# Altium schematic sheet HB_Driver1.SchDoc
size A4
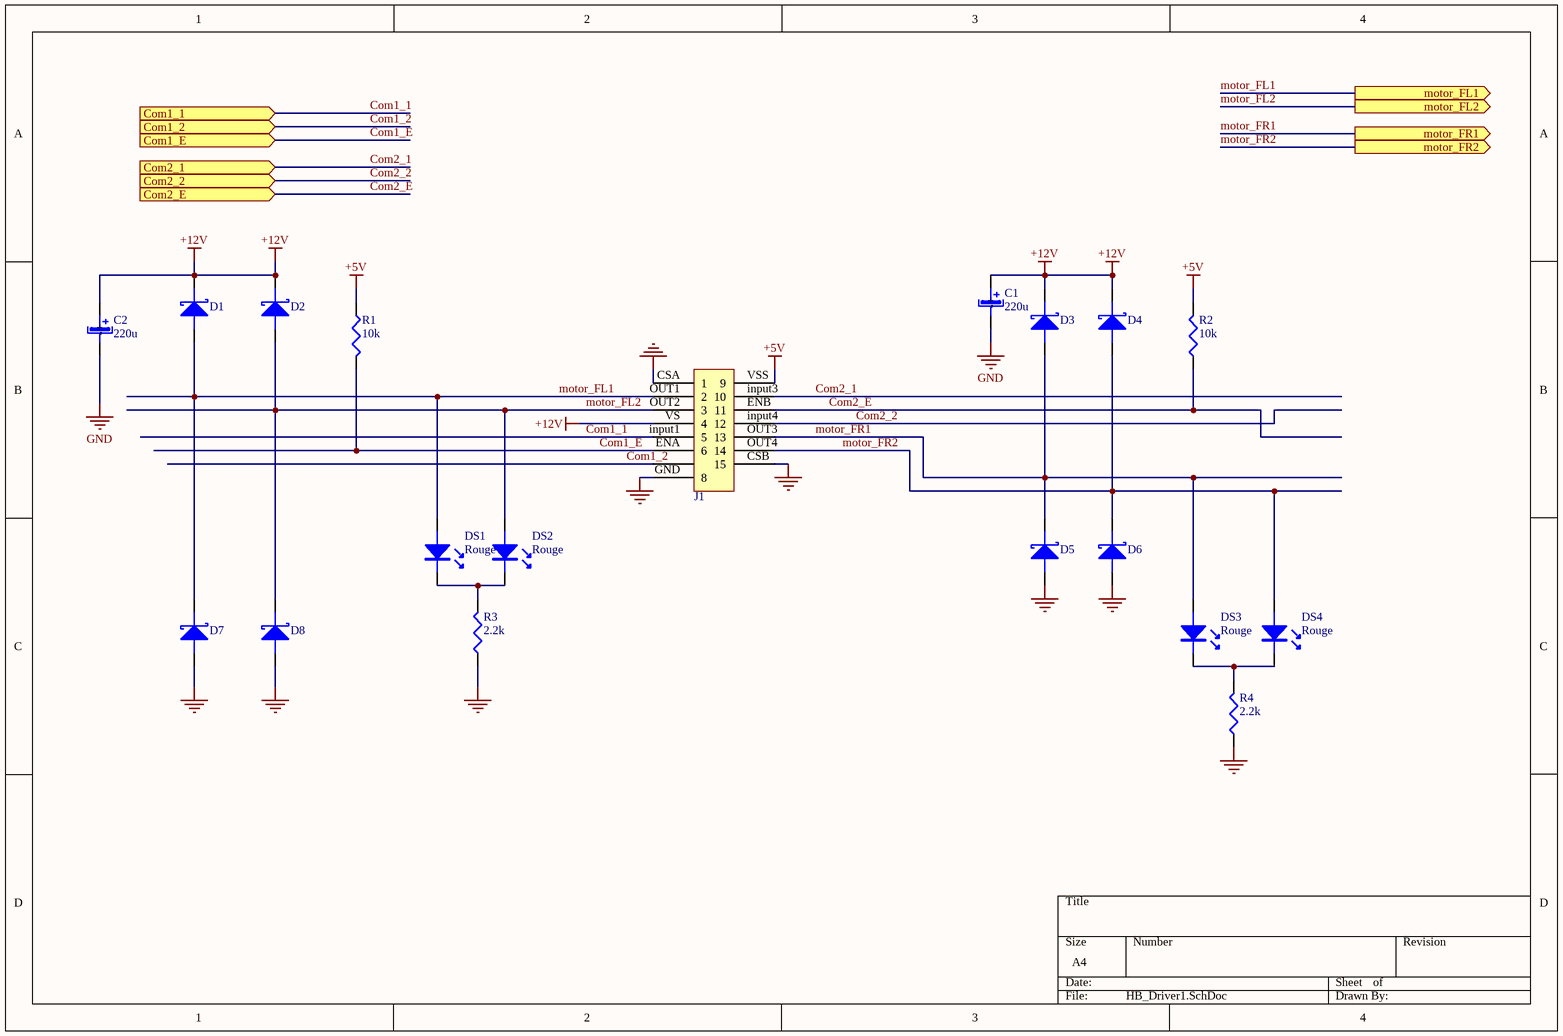
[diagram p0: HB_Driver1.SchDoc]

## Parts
C1  value 220u  [CAPAE0810X700N]  (hidden comment: Cap_220u)
C2  value 220u  [CAPAE0810X700N]  (hidden comment: Cap_220u)
D1  Diode Schottky  [SOD-123]  (value not drawn)
D2  Diode Schottky  [SOD-123]  (value not drawn)
D3  Diode Schottky  [SOD-123]  (value not drawn)
D4  Diode Schottky  [SOD-123]  (value not drawn)
D5  Diode Schottky  [SOD-123]  (value not drawn)
D6  Diode Schottky  [SOD-123]  (value not drawn)
D7  Diode Schottky  [SOD-123]  (value not drawn)
D8  Diode Schottky  [SOD-123]  (value not drawn)
DS1  Color: Rouge  [3.5X2.8X1.9]  (hidden comment: LED)
DS2  Color: Rouge  [3.5X2.8X1.9]  (hidden comment: LED)
DS3  Color: Rouge  [3.5X2.8X1.9]  (hidden comment: LED)
DS4  Color: Rouge  [3.5X2.8X1.9]  (hidden comment: LED)
J1  L298  [MultiWatt15]  (value not drawn)
R1  value 10k  [6-0805_L]  (hidden comment: Res_10k)
R2  value 10k  [6-0805_L]  (hidden comment: Res_10k)
R3  value 2.2k  [6-0805_L]  (hidden comment: Res_2.2k)
R4  value 2.2k  [6-0805_L]  (hidden comment: Res_2.2k)

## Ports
Com1_1 (in), Com1_2 (in), Com1_E (in), Com2_1 (in), Com2_2 (in), Com2_E (in), motor_FL1 (out), motor_FL2 (out), motor_FR1 (out), motor_FR2 (out)

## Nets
+5V: J1.VSS(9) R1.1 R2.2
+12V: C1.POS(+) C2.POS(+) D1.1(K) D2.1(K) D3.1(K) D4.1(K) J1.VS(4)
GND: C1.NEG(-) C2.NEG(-) D5.2(A) D6.2(A) D7.2(A) D8.2(A) J1.CSA(1) J1.CSB(15) J1.GND(8) R3.1 R4.1
Com1_1: J1.input1(5) ; port Com1_1
Com1_2: J1.input2 ; port Com1_2
Com1_E: J1.ENA(6) R1.2 ; port Com1_E
Com2_1: J1.input3(10) ; port Com2_1
Com2_2: J1.input4(12) ; port Com2_2
Com2_E: J1.ENB(11) R2.1 ; port Com2_E
motor_FL1: D1.2(A) D7.1(K) DS1.1(A) J1.OUT1(2) ; port motor_FL1
motor_FL2: D2.2(A) D8.1(K) DS2.1(A) J1.OUT2(3) ; port motor_FL2
motor_FR1: D3.2(A) D5.1(K) DS3.1(A) J1.OUT3(13) ; port motor_FR1
motor_FR2: D4.2(A) D6.1(K) DS4.1(A) J1.OUT4(14) ; port motor_FR2
NetDS1_2: DS1.2(K) DS2.2(K) R3.2
NetDS3_2: DS3.2(K) DS4.2(K) R4.2

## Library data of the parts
C1 C2 = Cap_220u: Condensateur polatisé; Type: Condensateur polarisé debout
J1 = L298: Connecteur
R1 R2 = Res_10k: Résistance standard
R3 R4 = Res_2.2k: Résistance standard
